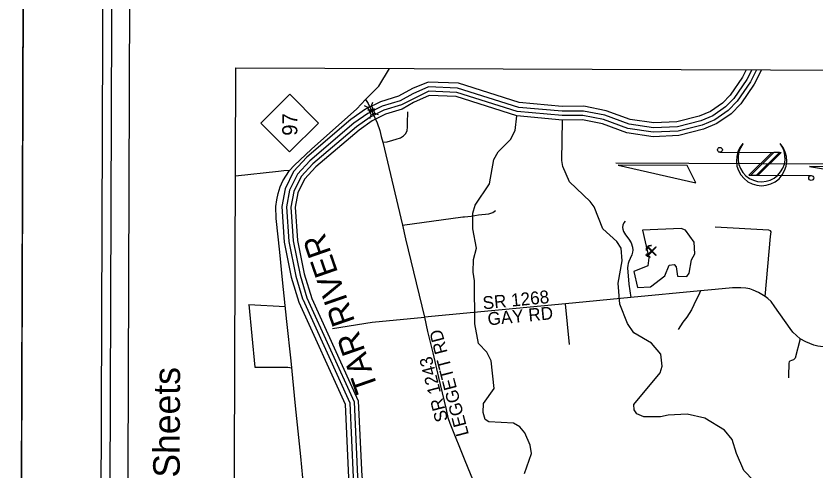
# Model space of a CAD drawing. Extents: x 2364794 to 2387902, y 795230 to 810426.
# Drawn here: x 2364794 to 2366377, y 801761 to 802661 of the extents above; entities that cross this region are included whole.
import ezdxf

# ---------------------------------------------------------------- set-up
doc = ezdxf.new("R2010")
doc.units = 0
for name, color, linetype in [('Default', 7, 'Continuous'), ('Mis Object Lines', 7, 'Continuous'), ('Old_Level_21', 7, 'Continuous'), ('Old_Level_22', 7, 'Continuous'), ('Old_Level_4', 7, 'Continuous'), ('Plan Sheet CELL', 7, 'Continuous'), ('Plot Label CELL', 7, 'Continuous'), ('User Information Notes CELL', 7, 'Continuous')]:
    doc.layers.add(name, color=color, linetype=linetype)

msp = doc.modelspace()

# ---------------------------------------------------------------- linework, layer by layer
at = {"layer": 'Default'}
for p, q in [((2365278.2, 802449.2), (2365335.3, 802505.9)), ((2365335.3, 802505.9), (2365392, 802448.8)), ((2365497, 802483.2), (2365499.8, 802490.3)), ((2365490.1, 802480.2), (2365483.1, 802482.9)), ((2365494, 802458), (2365496.7, 802465.1)), ((2365510.8, 802465.4), (2365503.8, 802468.2)), ((2365334.9, 802392.1), (2365278.2, 802449.2)), ((2365392, 802448.8), (2365334.9, 802392.1)), ((2365889.2, 802011.3), (2365881.2, 802092))]:
    msp.add_line(p, q, dxfattribs=at)
for points in [[(2365221.1, 800406.3), (2365228.7, 802558.1), (2367168.3, 802551.2), (2367160.7, 800399.4)], [(2365221.1, 800406.3), (2365228.7, 802558.1), (2367168.3, 802551.2), (2367160.7, 800399.4)], [(2365489.9, 802474.8), (2365503.1, 802477.1), (2365492.8, 802468.6), (2365497, 802474.3)], [(2365496.7, 802465.1), (2365490.1, 802480.2), (2365497.2, 802483.3), (2365503.8, 802468.2)], [(2366041.5, 802197.2), (2366041.3, 802198), (2366041.2, 802198.7), (2366041.1, 802199.7), (2366041.2, 802200.6), (2366041.6, 802201.9), (2366042.3, 802203.5), (2366043.3, 802204.8), (2366044.2, 802205.7), (2366045.3, 802206.4), (2366046.7, 802207), (2366047.7, 802207.3), (2366048.9, 802207.4), (2366050.2, 802207.4), (2366051.4, 802207.2), (2366049.8, 802206.9), (2366048.7, 802206.6), (2366047.9, 802206.3), (2366046.6, 802205.6), (2366045.5, 802204.8), (2366044.8, 802204.3), (2366043.7, 802203), (2366042.9, 802201.9), (2366042.3, 802200.6), (2366041.9, 802199.3), (2366041.7, 802198)], [(2366041.8, 802190.8), (2366039.8, 802188.8), (2366043.1, 802185.7), (2366048.8, 802184)], [(2366044.3, 802187.5), (2366043.5, 802188.4), (2366059.9, 802204.7), (2366060.7, 802203.8)], [(2366059.9, 802187.5), (2366060.7, 802188.3), (2366044.4, 802204.7), (2366043.6, 802203.9)]]:
    msp.add_lwpolyline(points, close=True, dxfattribs=at)
at = {"layer": 'Mis Object Lines'}
for points in [[(2365009.5, 810236.7), (2364972.8, 799876.6)], [(2365044.4, 810201.5), (2365009.3, 800261.6)]]:
    msp.add_lwpolyline(points, dxfattribs=at)
at = {"layer": 'Old_Level_21'}
msp.add_lwpolyline([(2364835.2, 810426.2), (2364793.5, 798638.3), (2372493.4, 798611.1), (2372535.1, 810399)], close=True, dxfattribs=at)
at = {"layer": 'Old_Level_22'}
msp.add_lwpolyline([(2372336.7, 798702.6), (2372377.9, 810368.1), (2364992.2, 810394.2), (2364951, 798728.7)], close=True, dxfattribs=at)
at = {"layer": 'Old_Level_4'}
for p, q in [((2366231.8, 802407.9), (2366232.3, 802408.6)), ((2366186.5, 802391.3), (2366308, 802390.9)), ((2366289.1, 802391), (2366243.6, 802345.8)), ((2366293.5, 802390.9), (2366248.1, 802345.8)), ((2366304.6, 802390.9), (2366259.2, 802345.8)), ((2366259.2, 802345.8), (2366304.6, 802390.9)), ((2366308, 802390.9), (2366262.6, 802345.8)), ((2366304.6, 802390.9), (2366293.5, 802390.9)), ((2366572.6, 802367.6), (2365980.3, 802369.7)), ((2366243.6, 802345.8), (2366367.2, 802345.4)), ((2366248.1, 802345.8), (2366259.2, 802345.8))]:
    msp.add_line(p, q, dxfattribs=at)
for points in [[(2365985.4, 802365.6), (2366139.1, 802331.2), (2366122.1, 802365.1)], [(2366363.9, 802363.5), (2366572.4, 802329.3), (2366546.1, 802362.9)]]:
    msp.add_lwpolyline(points, close=True, dxfattribs=at)
for centre in [(2366186.6, 802396.1), (2366367.3, 802340.6)]:
    msp.add_circle(centre, 4.83, dxfattribs=at)
for centre, radius, start, end in [((2366269, 802375), 49.8, 137.6376, 42.1917), ((2366269, 802379.8), 46.6, 142.8927, 38.4263)]:
    msp.add_arc(centre, radius, start, end, dxfattribs=at)
at = {"layer": 'Plan Sheet CELL'}
msp.add_line((2364793.5, 798638.3), (2364835.2, 810426.2), dxfattribs=at)
at = {"layer": 'Plot Label CELL'}
for p, q in [((2365511.7, 802521.8), (2365532.9, 802557)), ((2365484.9, 802495.5), (2365511.7, 802521.8)), ((2365254.5, 802090.2), (2365266.4, 801966.8)), ((2365254.5, 802090.2), (2365326.1, 802086.6))]:
    msp.add_line(p, q, dxfattribs=at)
for points in [[(2365334.6, 802355.6), (2365344.1, 802365.3), (2365378.3, 802397.7), (2365468, 802477.5), (2365484.9, 802495.5)], [(2365484.9, 802495.5), (2365490.5, 802488), (2365496, 802476.5)], [(2365496, 802476.5), (2365503.5, 802459.7), (2365508.2, 802449.7), (2365513.4, 802434.1), (2365516.5, 802422.8), (2365519.3, 802411.3), (2365558.1, 802247.5), (2365564.6, 802220.3), (2365575, 802176.5), (2365602, 802065.3)], [(2365519.3, 802411.3), (2365527.9, 802412.3), (2365539.5, 802415.3), (2365546.2, 802417.1), (2365554.7, 802419.8), (2365560.4, 802423.6), (2365564.7, 802428.2), (2365567.7, 802434.6), (2365568.5, 802440.9), (2365568.2, 802448.8), (2365568.9, 802471.1)], [(2365334.6, 802355.6), (2365323.5, 802354.9), (2365313, 802353.5), (2365227.9, 802343.9)], [(2365361.3, 801748), (2365357, 801789.9), (2365346.6, 801889.9), (2365338.1, 801979.1), (2365329.5, 802056.7), (2365320.7, 802139.5), (2365315.6, 802193.9), (2365308.4, 802260.2), (2365308, 802284.4), (2365309.7, 802297.6), (2365312.4, 802310), (2365316.5, 802323.2), (2365321.8, 802335.2), (2365334.6, 802355.6)], [(2365558.1, 802247.5), (2365678, 802263.6), (2365681.3, 802263.6), (2365694.4, 802265), (2365708.6, 802267.4), (2365729.1, 802269.5), (2365737.4, 802272.5), (2365742.8, 802276.4)], [(2365999.3, 802254.9), (2365996.4, 802251.9), (2365994.2, 802247), (2365993.7, 802242.8), (2365994.4, 802239.3), (2365995.9, 802234.5), (2365999.8, 802228.5), (2366006.4, 802219.6), (2366010.8, 802212.2), (2366013.4, 802203.8), (2366014.2, 802198.2), (2366013.9, 802193.6), (2366012.3, 802188.5), (2366009.3, 802181.7), (2366006.4, 802175.6), (2366005.2, 802171.2), (2366004.1, 802167.3), (2366003.7, 802162.7), (2366006.5, 802130.8), (2366010.6, 802104.5)], [(2366135.7, 802213.5), (2366118.3, 802237.1), (2366110, 802240.6), (2366033.7, 802237.1), (2366045.7, 802182.6), (2366044.2, 802167.1), (2366016.2, 802155.9), (2366023.5, 802124), (2366049.3, 802125.3), (2366077.9, 802147.4), (2366086.1, 802168.4), (2366096.1, 802169.4), (2366099.9, 802164.9), (2366102.7, 802146.7), (2366121, 802146), (2366125.5, 802152.4), (2366130.6, 802178.9), (2366136.9, 802190.8), (2366135.7, 802213.5)], [(2366276.3, 802106.2), (2366287, 802224.6), (2366287.7, 802234.3), (2366286.7, 802236.2), (2366283.1, 802237.6), (2366177.5, 802243.4)], [(2366645.6, 801975.3), (2366619.7, 801977.5), (2366588.7, 801981.6), (2366380.1, 802008.3), (2366372.7, 802010), (2366356.4, 802016.4), (2366345.4, 802022.7), (2366331.2, 802036.1), (2366325.5, 802043.1), (2366295.4, 802085.8), (2366288, 802096.3), (2366281.5, 802102.5), (2366276.3, 802106.2), (2366262.9, 802114.2), (2366252.2, 802119), (2366245.5, 802121.3), (2366238, 802122.6), (2366228.1, 802123.7), (2366211.6, 802123.6), (2366176.9, 802120.1), (2366148.3, 802117.4), (2366010.6, 802104.5), (2365881.2, 802092), (2365602, 802065.3)], [(2366148.3, 802117.4), (2366144.1, 802108.1), (2366139.6, 802099.7), (2366130.2, 802079.7), (2366121.2, 802065.7), (2366113, 802055.5), (2366103.7, 802041)], [(2365419.8, 802043.1), (2365498.5, 802055.4), (2365602, 802065.3)], [(2365602, 802065.3), (2365608.1, 802036.9), (2365618.3, 801994.7), (2365629.4, 801945.9), (2365637.1, 801915.6), (2365644.6, 801882.9), (2365648.3, 801867), (2365652, 801856.1), (2365681.6, 801782.1), (2365707.4, 801719.8), (2365726.7, 801669.6), (2365740.8, 801636), (2365751.2, 801611), (2365758, 801597), (2365768.5, 801582.7), (2365799.1, 801549.6), (2365800.2, 801548.4)], [(2366345.4, 802022.7), (2366335.6, 801984.2), (2366332.3, 801981), (2366328.4, 801979.5), (2366325.2, 801978.4), (2366323.8, 801977), (2366323.3, 801974.2), (2366323.1, 801969.1), (2366322.5, 801954.4), (2366322.3, 801945.4)], [(2365266.4, 801966.8), (2365331.6, 801966.4), (2365339.3, 801965.5)]]:
    msp.add_lwpolyline(points, dxfattribs=at)
at = {"layer": 'User Information Notes CELL'}
for p, q in [((2365874.6, 802472.5), (2365788.5, 802480)), ((2365874.5, 802482.1), (2365789.3, 802489.5)), ((2365874.8, 802455.1), (2365784.4, 802463.3)), ((2365874.7, 802463.9), (2365785.2, 802472))]:
    msp.add_line(p, q, dxfattribs=at)
for points in [[(2366238.8, 802554.5), (2366231.5, 802539.9), (2366206.9, 802504), (2366191.4, 802488.2), (2366167.7, 802471.8), (2366145.8, 802462.5), (2366101.3, 802451.4), (2366055.8, 802449.3), (2366009.1, 802456.2), (2365961.3, 802473.6), (2365917.2, 802482.5), (2365874.5, 802482.1)], [(2366249.5, 802554.5), (2366239.7, 802535), (2366214.4, 802497.9), (2366197.6, 802480.9), (2366172.4, 802463.3), (2366148.8, 802453.4), (2366102.7, 802441.8), (2366055.3, 802439.7), (2366006.7, 802446.9), (2365958.7, 802464.4), (2365916.3, 802472.9), (2365874.6, 802472.5)], [(2366259.1, 802554.4), (2366247.1, 802530.6), (2366221, 802492.4), (2366203.1, 802474.2), (2366176.6, 802455.8), (2366151.5, 802445.2), (2366104, 802433.3), (2366054.8, 802431), (2366004.6, 802438.5), (2365956.4, 802456.1), (2365915.4, 802464.3), (2365874.7, 802463.9)], [(2366268.9, 802554.4), (2366254.7, 802526.2), (2366227.8, 802486.8), (2366208.8, 802467.5), (2366180.8, 802448), (2366154.3, 802436.9), (2366105.3, 802424.6), (2366054.4, 802422.2), (2366002.4, 802430), (2365954, 802447.6), (2365914.6, 802455.5), (2365874.8, 802455.1)], [(2365789.3, 802489.5), (2365669.2, 802527.7), (2365609.5, 802530), (2365578.3, 802517.2), (2365550.6, 802502.1)], [(2365788.5, 802480), (2365667.6, 802518.4), (2365610.1, 802520.7), (2365579.2, 802507.1), (2365553.5, 802493.2)], [(2365785.2, 802472), (2365666, 802509.8), (2365610.5, 802512), (2365556.4, 802485.1)], [(2365550.6, 802502.1), (2365514.8, 802491.2), (2365485, 802476.3), (2365456.1, 802456.1), (2365368.9, 802381.4), (2365342.7, 802353.6), (2365326.1, 802319.3), (2365319.4, 802284.2), (2365324.3, 802213.6), (2365338.2, 802144.3), (2365353.5, 802095)], [(2365553.5, 802493.2), (2365518.3, 802482.6), (2365489.8, 802468.3), (2365461.8, 802448.7), (2365375.3, 802374.7), (2365350.4, 802348.3), (2365335, 802316.4), (2365328.7, 802283.6), (2365333.5, 802214.8), (2365347.2, 802146.6), (2365360.7, 802101.9)], [(2365784.4, 802463.3), (2365664.6, 802501.4), (2365611, 802503.5), (2365580.1, 802489.9), (2365557.5, 802476.5)], [(2365556.4, 802485.1), (2365521.5, 802474.5), (2365494.2, 802460.9), (2365467.1, 802441.9), (2365381.3, 802368.4), (2365357.6, 802343.3), (2365343.3, 802313.6), (2365337.4, 802283.1), (2365342.1, 802216), (2365355.6, 802148.7), (2365369.2, 802103.7)], [(2365557.5, 802476.5), (2365524.7, 802466.6), (2365498.6, 802453.5), (2365472.4, 802435.1), (2365387.2, 802362.3), (2365364.7, 802338.4), (2365351.4, 802310.9), (2365346, 802282.6), (2365350.6, 802217.1), (2365363.8, 802150.8), (2365379, 802102.6)], [(2365799.6, 801756.7), (2365813.6, 801795.9), (2365810.8, 801812.3), (2365800.6, 801836.8), (2365790.5, 801848.5), (2365778.4, 801855.7), (2365729.4, 801858.8), (2365722.1, 801863.3), (2365718, 801876.9), (2365718.8, 801895.1), (2365739.6, 801924.5), (2365733.6, 801979.1), (2365725, 801996.4), (2365708.6, 802013.5), (2365701.8, 802052.6), (2365701.1, 802137.3), (2365698.3, 802154.6), (2365698.8, 802179.2), (2365704.8, 802202.1), (2365697.3, 802240.2), (2365697.9, 802271.2), (2365702.3, 802286.7), (2365730.9, 802328.9), (2365739.5, 802377.3), (2365747.6, 802392), (2365772.2, 802416.8), (2365781.2, 802434.1), (2365784.4, 802463.3)], [(2366016, 801892.7), (2366068.2, 801955.1), (2366072.4, 801968.8), (2366069.7, 801992.4), (2366051.3, 802014.2), (2366016.4, 802034.7), (2366003.6, 802052.8), (2365988.5, 802090.9), (2365985.1, 802132.8), (2365993.2, 802176.6), (2365991.2, 802202.1), (2365982.8, 802214.7), (2365954.9, 802240), (2365937.5, 802283.6), (2365930, 802294.4), (2365888.7, 802333.2), (2365875.7, 802363.2), (2365873.5, 802374.9), (2365874.8, 802455.1)], [(2365353.5, 802095), (2365444.8, 801893.8), (2365451.6, 801747.6), (2365456.5, 801722.9), (2365476.7, 801676.1), (2365511.5, 801632.9), (2365585.2, 801577), (2365595.5, 801566.9), (2365614.2, 801536.7), (2365628, 801505.5), (2365638.5, 801456.7), (2365638, 801429.8), (2365633.5, 801402.1), (2365624, 801376)], [(2365360.7, 802101.9), (2365361, 802100.8), (2365454, 801896), (2365460.9, 801748.7), (2365465.5, 801725.6), (2365484.8, 801681), (2365518, 801639.6), (2365591.2, 801584), (2365602.8, 801572.7), (2365622.4, 801541.1), (2365636.9, 801508.4), (2365647.8, 801457.6), (2365647.3, 801428.9), (2365642.5, 801399.8), (2365632.7, 801372.8)], [(2365369.2, 802103.7), (2365462.5, 801898.1), (2365469.5, 801749.8), (2365473.8, 801728.2), (2365492.2, 801685.5), (2365524.1, 801645.8), (2365596.9, 801590.6), (2365609.6, 801578.2), (2365630.1, 801545.2), (2365645.2, 801511.1), (2365656.5, 801458.4), (2365655.9, 801428.1), (2365650.9, 801397.6), (2365640.9, 801369.9)], [(2365379, 802102.6), (2365470.9, 801900.1), (2365478, 801750.8), (2365481.9, 801730.8), (2365499.6, 801689.9), (2365530.1, 801652), (2365602.5, 801597), (2365616.3, 801583.5), (2365637.6, 801549.1), (2365653.3, 801513.7), (2365665, 801459.3), (2365664.4, 801427.3), (2365659.2, 801395.4), (2365648.9, 801367)], [(2366462.4, 801518), (2366392, 801712.2), (2366378.4, 801710.3), (2366368.6, 801705.6), (2366333.8, 801705.3), (2366290.1, 801721.4), (2366253.4, 801741.9), (2366234, 801762.7), (2366219.1, 801796.2), (2366210.6, 801823.4), (2366195.9, 801842.4), (2366156.6, 801865.7), (2366121.9, 801873.6), (2366084.3, 801871.5), (2366068.9, 801868.6), (2366036.3, 801868.2), (2366022.4, 801874.5), (2366016.7, 801882.6), (2366016, 801892.7)]]:
    msp.add_lwpolyline(points, dxfattribs=at)

# ---------------------------------------------------------------- texts
at = {"layer": 'Default'}
for s, height, rotation, p in [('97', 29.9, 89.7976, (2365350.3, 802424)), ('TAR RIVER', 45.93, 109.1673, (2365510.9, 801924.9)), ('LEGGETT RD', 25.36, 104.5468, (2365690, 801833.5)), ('SR 1243 ', 25.36, 104.5468, (2365649, 801861.9))]:
    msp.add_text(s, height=height, rotation=rotation, dxfattribs=at).set_placement(p)
at = {"layer": 'Mis Object Lines'}
msp.add_text('See Sheet 1-A For Index of Sheets', height=52.5, rotation=89.7976, dxfattribs=at).set_placement((2365114.4, 800877.9))
at = {"layer": 'Plot Label CELL'}
for s, p in [('SR 1268', (2365718.3, 802080.8)), ('GAY RD', (2365728, 802049.1))]:
    msp.add_text(s, height=25.36, rotation=5.5284, dxfattribs=at).set_placement(p)

doc.saveas('drawing.dxf')
